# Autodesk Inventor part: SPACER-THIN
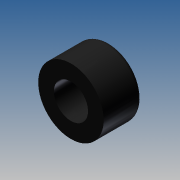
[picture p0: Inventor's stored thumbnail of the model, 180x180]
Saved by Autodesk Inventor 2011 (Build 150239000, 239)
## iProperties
Created: 2008-05
Part Number: SPACER-THIN
Document SubType Name: Modeling
Density: 1 g/cm^3
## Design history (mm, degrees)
feature "Base1"
body "Solid1"
